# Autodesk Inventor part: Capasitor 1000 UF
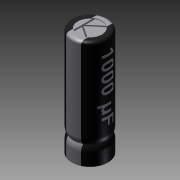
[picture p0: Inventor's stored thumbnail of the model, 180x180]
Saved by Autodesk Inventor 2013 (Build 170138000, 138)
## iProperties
Company: Autodesk Inc.
Created: 2005-12
Part Number: Capasitor 1000 UF
Document SubType Name: Modeling
Designer: Autodesk Inc.
Density: 1 g/cm^3
Mass: 0.502542 g
Surface Area: 3.97565 cm^2
Volume: 0.502542 cm^3
Material: Allgemein
Title: Personal Computer
Author: Autodesk Inc.
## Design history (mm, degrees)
sketch "Sketch1"
  geometry: L1 (0, 4.2)-(0, -4.2) reference; L2 (-4.2, 0)-(4.2, 0) reference; C1 r 3 at (0, 0)
  constraints: 2 midpoint, 1 centre point
  dimensions: "d0" = 6 diameter of C1
extrude "Extrusion1" new body sketch "Sketch1" distance "d1" = 18; taper "d2" = 0 deg
revolve "Revolution1" stored, may be unused: angle "d19" = 90 deg
sketch "Sketch2"
  geometry: C1 r 3 at (0, 0) reference; C2 r 2 at (0, 0)
  constraints: 1 centre point, 1 coincident
  dimensions: "d3" = 1 radial gap between concentric circles of C2 C1
extrude "Extrusion2" cut sketch "Sketch2" distance "d4" = 0.1; taper "d5" = 0 deg
sketch "Sketch3"
  geometry: L1 (-1.157, 1.816)-(-0.869, 1.816); L2 (-0.869, 1.816)-(-0.869, -1.835); L3 (-0.869, -1.835)-(-1.157, -1.835); L4 (-1.157, -1.835)-(-1.157, 1.816); L5 (-0.869, -0.208)-(-1.03, -0.018); L6 (-1.03, -0.018)-(1.082, 1.758); L7 (1.082, 1.758)-(1.242, 1.567); L8 (1.242, 1.567)-(-0.869, -0.208); L9 (-0.869, -0.208)-(-0.985, -0.382); L10 (-0.985, -0.382)-(1.34, -1.926); L11 (1.34, -1.926)-(1.455, -1.753); L12 (1.455, -1.753)-(-0.869, -0.208); 1 further point
  constraints: 24 end point, 6 parallel, 3 perpendicular, 1 horizontal, 1 point on line, 2 other
extrude "Extrusion3" cut sketch "Sketch3" distance "d6" = 0.05; taper "d7" = 0 deg
fillet "Fillet1" dims "d8" = 0.5
sketch "Sketch5"
  geometry: L1 (1.25, 1.561)-(1.25, -4); L2 (1.25, -4)-(-1.25, -4); L3 (-1.25, -4)-(-1.25, 1.561); L4 (0, -5.4)-(0, 4.4) reference; A1 r 2 centre (0, 0) between (-1.25, 1.561) and (1.25, 1.561) reference; 3 further points
  constraints: 6 end point, 2 point on circle, 1 coincident, 1 parallel, 1 point on line, 1 vertical alignment, 2 other
  dimensions: "d12" = 1 distance from line of L2 point (0, -3); "d13" = 2.5 distance of L1.end L2.end
split "Split1" sketch "Sketch5"
workplane "Work Plane1"
sketch "Sketch4"
  geometry: L1 (-16.519, 1.302)-(-0.91, 1.302); L2 (-0.91, 1.302)-(-0.91, -2.537); L3 (-0.91, -2.537)-(-16.519, -2.537); L4 (-16.519, -2.537)-(-16.519, 1.302)
  constraints: 2 other
emboss "Emboss1" sketch "Sketch4" dims "d10" = 0.05, "d11" = 0
body "Solid1"
sketch "Sketch6"
  geometry: L1 (0, 21.6)-(0, -3.6) reference; L2 (3, 0)-(3, 18) reference; L3 (3, 4)-(3, 2); L4 (3, 3)-(2.7, 3); L5 (-3, 0)-(3, 0) reference; A1 r 1.817 centre (1.183, 4) between (2.7, 3) and (3, 4); A2 r 1.817 centre (1.183, 2) between (3, 2) and (2.7, 3); 1 further point
  constraints: 4 end point, 4 point on circle, 2 centre point, 2 point on line, 2 tangent, 1 collinear, 1 horizontal, 1 midpoint
  dimensions: "d16" = 2 distance of L3.start L3.end; "d17" = 3 distance between parallel lines of L5 L4; "d18" = 0.3 distance of L4.start L4.end
